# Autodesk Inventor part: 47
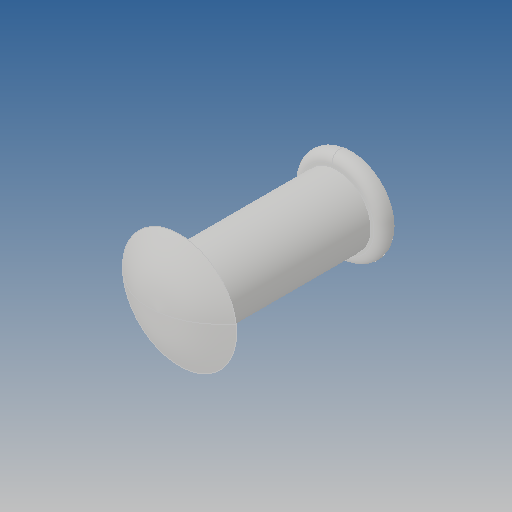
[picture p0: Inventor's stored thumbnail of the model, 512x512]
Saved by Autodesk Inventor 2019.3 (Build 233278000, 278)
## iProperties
Created: 2017-08
Part Number: 47
Material: Ogólny
Document SubType Name: Modeling
Designer: Admin
Density: 1 g/cm^3
Appearance: Domyślna
Author: Admin
Revision Number: ÈÎºÎ
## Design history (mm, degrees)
feature "ÊäÈë1"
node "Bryła1"
